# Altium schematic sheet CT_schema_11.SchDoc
size 147 x 119 mm
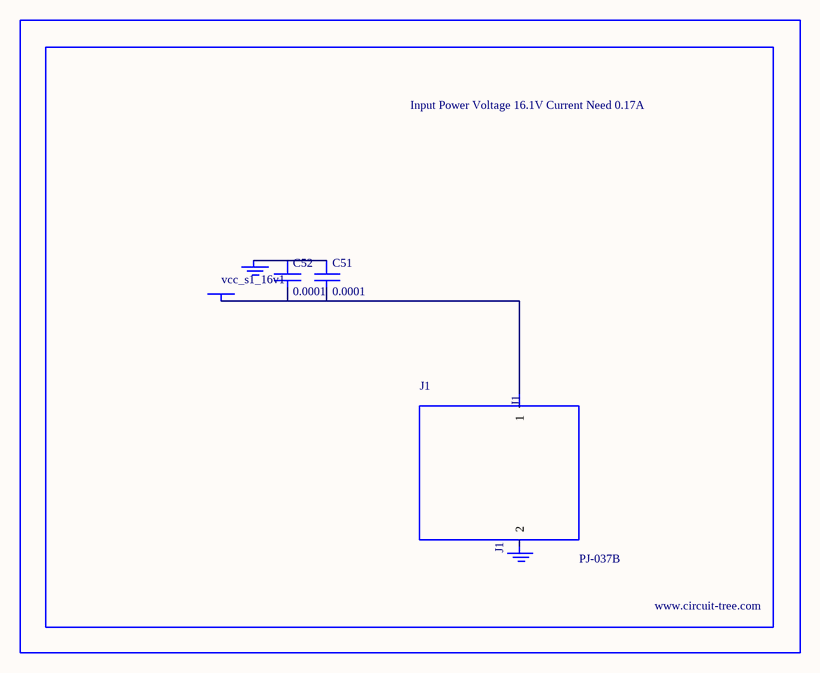
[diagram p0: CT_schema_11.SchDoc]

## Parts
BORDER10  (no value)
C51  0.0001  [EXV-9H]
C52  0.0001  [EXV-9H]
GND_INSTANCE_10_0  (no value)
GND_INSTANCE_10_1  (no value)
J1  PJ-037B  [PJ-037B_PACKAGE]
POWER_INSTANCE_10_0  vcc_s1_16v1

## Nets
NetC51_1: C51.1 C52.1 GND_INSTANCE_10_0.0(GND)
NetC51_2: C51.2 C52.2 J1.1 POWER_INSTANCE_10_0.0(PWR)

Not connected (* = marked no-connect by the designer): GND_INSTANCE_10_1 0(GND); J1 2

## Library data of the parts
BORDER10 = BORDER_PAGE10
C51 C52 = EDK107M035A9HAA
GND_INSTANCE_10_0 GND_INSTANCE_10_1 = GND
POWER_INSTANCE_10_0 = PWR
